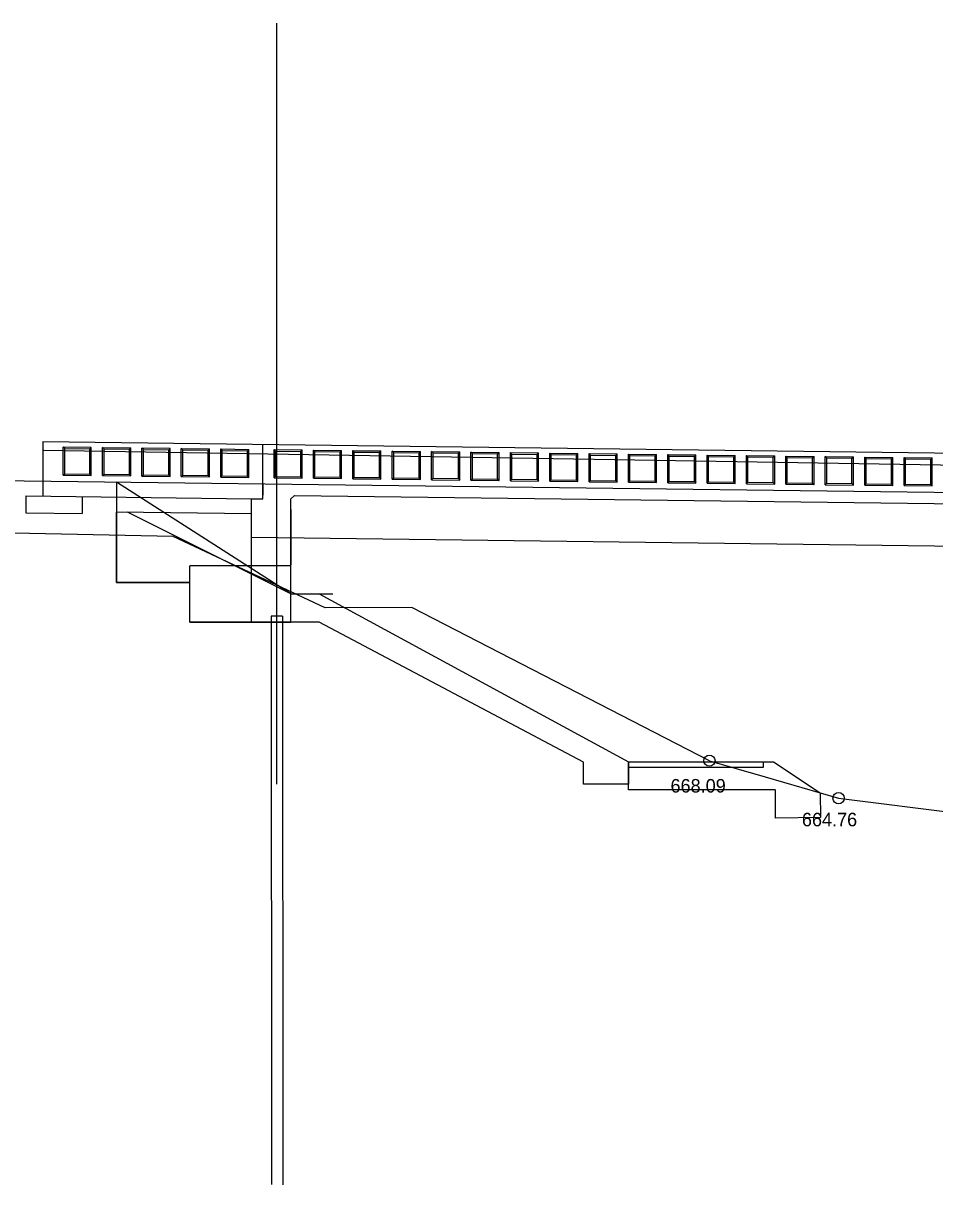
# Model space of a CAD drawing. Extents: x -845213 to 595816, y -257022 to 229056.
# Drawn here: x 595397.5 to 595478.6, y 228657.3 to 228760.5 of the extents above; entities that cross this region are included whole.
import ezdxf

# ---------------------------------------------------------------- set-up
doc = ezdxf.new("R2010")
doc.units = 0
for name, color, linetype in [('B_CL', 7, 'Continuous'), ('B_CONC', 7, 'Continuous'), ('B_CONC_HIDDEN', 7, 'Continuous'), ('B_CONST', 7, 'Continuous'), ('B_GROUNDLINE', 7, 'Continuous'), ('B_MISC', 7, 'Continuous'), ('B_PATTERN', 7, 'Continuous'), ('B_PILES_HIDDEN', 7, 'Continuous'), ('B_PROP', 7, 'Continuous'), ('B_SCREEN', 7, 'Continuous'), ('E_STRUCT', 7, 'Continuous'), ('P_E_PROF', 7, 'Continuous'), ('P_PROF', 7, 'Continuous')]:
    doc.layers.add(name, color=color, linetype=linetype)

msp = doc.modelspace()

# ---------------------------------------------------------------- linework, layer by layer
at = {"layer": 'B_CL'}
for p, q in [((595420.07, 228692.87), (595420.07, 228760.49)), ((595420.07, 228707.28), (595420.07, 228715.45))]:
    msp.add_line(p, q, dxfattribs=at)
at = {"layer": 'B_CONC'}
for p, q in [((595399.25, 228723.31), (595719.75, 228719.29)), ((595399.25, 228723.31), (595399.25, 228719.81)), ((595418.82, 228719.56), (595418.82, 228723.06)), ((595405.82, 228719.72), (595405.82, 228710.78)), ((595421.32, 228718.23), (595421.62, 228718.53)), ((595421.62, 228718.53), (595696.95, 228715.07)), ((595421.32, 228707.28), (595421.32, 228718.23)), ((595417.81, 228714.82), (595700.75, 228711.28)), ((595412.32, 228707.28), (595412.32, 228712.28)), ((595417.82, 228712.28), (595412.32, 228712.28)), ((595405.82, 228710.78), (595412.32, 228710.78))]:
    msp.add_line(p, q, dxfattribs=at)
at = {"layer": 'B_CONC_HIDDEN'}
for p, q in [((595418.82, 228719.56), (595418.82, 228718.56)), ((595417.82, 228718.24), (595418.82, 228718.23)), ((595417.82, 228707.32), (595417.82, 228718.24))]:
    msp.add_line(p, q, dxfattribs=at)
at = {"layer": 'B_CONST'}
for p in [(595421.32, 228717.28), (595421.32, 228707.37)]:
    msp.add_line(p, (595421.32, 228712.37), dxfattribs=at)
at = {"layer": 'B_GROUNDLINE'}
msp.add_lwpolyline([(595421.32, 228709.78), (595405.82, 228719.72)], dxfattribs=at)
at = {"layer": 'B_MISC'}
for p, q in [((595417.82, 228716.88), (595405.82, 228717.05)), ((595405.82, 228710.78), (595405.82, 228717.05)), ((595421.32, 228709.78), (595406.8, 228717.04)), ((595417.82, 228707.28), (595417.82, 228716.88)), ((595421.32, 228712.28), (595412.32, 228712.28)), ((595412.32, 228707.28), (595412.32, 228712.28)), ((595421.32, 228707.28), (595421.32, 228712.28)), ((595412.32, 228710.78), (595405.82, 228710.78)), ((595421.32, 228707.28), (595421.32, 228709.88)), ((595421.32, 228709.78), (595425.04, 228709.78)), ((595421.32, 228707.28), (595412.32, 228707.28))]:
    msp.add_line(p, q, dxfattribs=at)
for centre in [(595458.52, 228694.96), (595470, 228691.63)]:
    msp.add_circle(centre, 0.5, dxfattribs=at)
at = {"layer": 'B_PATTERN'}
for points in [[(595421.32, 228707.28), (595421.32, 228709.78), (595423.82, 228709.78), (595451.32, 228694.87), (595451.32, 228692.87), (595447.32, 228692.87), (595447.32, 228694.83), (595423.82, 228707.28)], [(595451.32, 228692.37), (595451.32, 228694.87), (595464.22, 228694.87), (595468.36, 228692.09), (595468.39, 228689.91), (595464.39, 228689.84), (595464.39, 228692.34), (595464.36, 228692.37)]]:
    msp.add_lwpolyline(points, close=True, dxfattribs=at)
at = {"layer": 'B_PILES_HIDDEN'}
for p, q in [((595420.57, 228707.79), (595419.57, 228707.81)), ((595419.57, 228707.81), (595419.59, 228657.3)), ((595420.57, 228707.79), (595420.59, 228657.28))]:
    msp.add_line(p, q, dxfattribs=at)
at = {"layer": 'B_PROP'}
for p, q in [((595451.32, 228694.87), (595463.32, 228694.87)), ((595451.32, 228694.37), (595451.32, 228694.87)), ((595463.32, 228694.37), (595463.32, 228694.87)), ((595451.32, 228694.37), (595463.32, 228694.37))]:
    msp.add_line(p, q, dxfattribs=at)
at = {"layer": 'B_SCREEN'}
for p, q in [((595403.57, 228722.8), (595401.07, 228722.83)), ((595401.07, 228720.33), (595401.07, 228722.83)), ((595401.2, 228722.7), (595401.07, 228722.83)), ((595401.2, 228722.7), (595403.45, 228722.68)), ((595401.2, 228720.45), (595401.2, 228722.7)), ((595403.45, 228722.68), (595403.57, 228722.8)), ((595403.45, 228720.43), (595403.45, 228722.68)), ((595403.57, 228720.3), (595403.57, 228722.8)), ((595404.57, 228720.29), (595404.57, 228722.79)), ((595404.57, 228722.79), (595407.07, 228722.76)), ((595404.7, 228722.66), (595404.57, 228722.79)), ((595404.7, 228722.66), (595406.95, 228722.63)), ((595404.7, 228720.41), (595404.7, 228722.66)), ((595406.95, 228722.63), (595407.07, 228722.76)), ((595406.95, 228720.38), (595406.95, 228722.63)), ((595407.07, 228720.26), (595407.07, 228722.76)), ((595410.57, 228722.71), (595408.07, 228722.74)), ((595408.07, 228720.24), (595408.07, 228722.74)), ((595408.2, 228722.62), (595408.07, 228722.74)), ((595408.2, 228722.62), (595410.45, 228722.59)), ((595408.2, 228720.37), (595408.2, 228722.62)), ((595410.45, 228722.59), (595410.57, 228722.71)), ((595410.45, 228720.34), (595410.45, 228722.59)), ((595410.57, 228720.21), (595410.57, 228722.71)), ((595411.57, 228720.2), (595411.57, 228722.7)), ((595411.57, 228722.7), (595414.07, 228722.67)), ((595411.7, 228722.57), (595411.57, 228722.7)), ((595411.7, 228722.57), (595413.95, 228722.54)), ((595411.7, 228720.32), (595411.7, 228722.57)), ((595413.95, 228722.54), (595414.07, 228722.67)), ((595413.95, 228720.29), (595413.95, 228722.54)), ((595414.07, 228720.17), (595414.07, 228722.67)), ((595415.07, 228720.16), (595415.07, 228722.66)), ((595415.07, 228722.66), (595417.57, 228722.62)), ((595415.2, 228722.53), (595415.07, 228722.66)), ((595415.2, 228722.53), (595417.45, 228722.5)), ((595415.2, 228720.28), (595415.2, 228722.53)), ((595417.45, 228722.5), (595417.57, 228722.62)), ((595417.57, 228720.12), (595417.57, 228722.62)), ((595419.82, 228720.1), (595419.82, 228722.6)), ((595419.82, 228722.6), (595422.32, 228722.57)), ((595419.95, 228722.47), (595419.82, 228722.6)), ((595422.2, 228722.44), (595422.32, 228722.57)), ((595422.32, 228720.07), (595422.32, 228722.57)), ((595423.32, 228720.05), (595423.32, 228722.55)), ((595423.32, 228722.55), (595425.82, 228722.52)), ((595423.45, 228722.43), (595423.32, 228722.55)), ((595425.7, 228722.4), (595425.82, 228722.52)), ((595425.82, 228720.02), (595425.82, 228722.52)), ((595426.82, 228720.01), (595426.82, 228722.51)), ((595426.82, 228722.51), (595429.32, 228722.48)), ((595426.95, 228722.38), (595426.82, 228722.51)), ((595417.45, 228720.25), (595417.45, 228722.5)), ((595419.95, 228722.47), (595422.2, 228722.44)), ((595419.95, 228720.22), (595419.95, 228722.47)), ((595422.2, 228720.19), (595422.2, 228722.44)), ((595423.45, 228722.43), (595425.7, 228722.4)), ((595423.45, 228720.18), (595423.45, 228722.43)), ((595425.7, 228720.15), (595425.7, 228722.4)), ((595426.95, 228722.38), (595429.2, 228722.36)), ((595426.95, 228720.13), (595426.95, 228722.38)), ((595429.2, 228722.36), (595429.32, 228722.48)), ((595429.2, 228720.11), (595429.2, 228722.36)), ((595429.32, 228719.98), (595429.32, 228722.48)), ((595430.32, 228719.97), (595430.32, 228722.47)), ((595430.32, 228722.47), (595432.82, 228722.44)), ((595430.45, 228722.34), (595430.32, 228722.47)), ((595430.45, 228722.34), (595432.7, 228722.31)), ((595430.45, 228720.09), (595430.45, 228722.34)), ((595432.7, 228722.31), (595432.82, 228722.44)), ((595432.7, 228720.06), (595432.7, 228722.31)), ((595432.82, 228719.94), (595432.82, 228722.44)), ((595433.82, 228719.92), (595433.82, 228722.42)), ((595433.82, 228722.42), (595436.32, 228722.39)), ((595433.95, 228722.3), (595433.82, 228722.42)), ((595433.95, 228722.3), (595436.2, 228722.27)), ((595433.95, 228720.05), (595433.95, 228722.3)), ((595436.2, 228722.27), (595436.32, 228722.39)), ((595436.2, 228720.02), (595436.2, 228722.27)), ((595436.32, 228719.89), (595436.32, 228722.39)), ((595437.32, 228719.88), (595437.32, 228722.38)), ((595437.32, 228722.38), (595439.82, 228722.35)), ((595437.45, 228722.25), (595437.32, 228722.38)), ((595437.45, 228722.25), (595439.69, 228722.22)), ((595437.45, 228720), (595437.45, 228722.25)), ((595439.69, 228722.22), (595439.82, 228722.35)), ((595439.69, 228719.97), (595439.69, 228722.22)), ((595439.82, 228719.85), (595439.82, 228722.35)), ((595440.82, 228719.84), (595440.82, 228722.34)), ((595440.82, 228722.34), (595443.32, 228722.3)), ((595440.94, 228722.21), (595440.82, 228722.34)), ((595440.94, 228722.21), (595443.19, 228722.18)), ((595440.94, 228719.96), (595440.94, 228722.21)), ((595443.19, 228722.18), (595443.32, 228722.3)), ((595443.19, 228719.93), (595443.19, 228722.18)), ((595443.32, 228719.8), (595443.32, 228722.3)), ((595444.32, 228719.79), (595444.32, 228722.29)), ((595444.32, 228722.29), (595446.82, 228722.26)), ((595444.44, 228722.16), (595444.32, 228722.29)), ((595444.44, 228722.16), (595446.69, 228722.14)), ((595444.44, 228719.92), (595444.44, 228722.16)), ((595446.69, 228722.14), (595446.82, 228722.26)), ((595446.69, 228719.89), (595446.69, 228722.14)), ((595446.82, 228719.76), (595446.82, 228722.26)), ((595447.82, 228722.25), (595450.32, 228722.22)), ((595447.82, 228719.75), (595447.82, 228722.25)), ((595447.94, 228722.12), (595447.82, 228722.25)), ((595447.94, 228722.12), (595450.19, 228722.09)), ((595447.94, 228719.87), (595447.94, 228722.12)), ((595450.19, 228722.09), (595450.32, 228722.22)), ((595450.19, 228719.84), (595450.19, 228722.09)), ((595450.32, 228719.72), (595450.32, 228722.22)), ((595451.32, 228719.7), (595451.32, 228722.2)), ((595451.32, 228722.2), (595453.82, 228722.17)), ((595451.44, 228722.08), (595451.32, 228722.2)), ((595451.44, 228722.08), (595453.69, 228722.05)), ((595451.44, 228719.83), (595451.44, 228722.08)), ((595453.69, 228722.05), (595453.82, 228722.17)), ((595453.69, 228719.8), (595453.69, 228722.05)), ((595453.82, 228719.67), (595453.82, 228722.17)), ((595454.82, 228719.66), (595454.82, 228722.16)), ((595454.82, 228722.16), (595457.32, 228722.13)), ((595454.94, 228722.03), (595454.82, 228722.16)), ((595454.94, 228722.03), (595457.19, 228722.01)), ((595454.94, 228719.78), (595454.94, 228722.03)), ((595457.19, 228722.01), (595457.32, 228722.13)), ((595457.19, 228719.76), (595457.19, 228722.01)), ((595457.32, 228719.63), (595457.32, 228722.13)), ((595458.32, 228719.62), (595458.32, 228722.12)), ((595458.32, 228722.12), (595460.82, 228722.08)), ((595458.44, 228721.99), (595458.32, 228722.12)), ((595458.44, 228721.99), (595460.69, 228721.96)), ((595458.44, 228719.74), (595458.44, 228721.99)), ((595460.69, 228721.96), (595460.82, 228722.08)), ((595460.69, 228719.71), (595460.69, 228721.96)), ((595460.82, 228719.58), (595460.82, 228722.08)), ((595461.82, 228719.57), (595461.82, 228722.07)), ((595461.82, 228722.07), (595464.32, 228722.04)), ((595461.94, 228721.95), (595461.82, 228722.07)), ((595461.94, 228721.95), (595464.19, 228721.92)), ((595461.94, 228719.7), (595461.94, 228721.95)), ((595464.19, 228721.92), (595464.32, 228722.04)), ((595464.19, 228719.67), (595464.19, 228721.92)), ((595464.32, 228719.54), (595464.32, 228722.04)), ((595465.32, 228719.53), (595465.32, 228722.03)), ((595465.32, 228722.03), (595467.82, 228722)), ((595465.44, 228721.9), (595465.32, 228722.03)), ((595465.44, 228721.9), (595467.69, 228721.87)), ((595465.44, 228719.65), (595465.44, 228721.9)), ((595467.69, 228721.87), (595467.82, 228722)), ((595467.69, 228719.62), (595467.69, 228721.87)), ((595467.82, 228719.5), (595467.82, 228722)), ((595468.82, 228719.48), (595468.82, 228721.98)), ((595468.82, 228721.98), (595471.32, 228721.95)), ((595468.94, 228721.86), (595468.82, 228721.98)), ((595468.94, 228721.86), (595471.19, 228721.83)), ((595468.94, 228719.61), (595468.94, 228721.86)), ((595471.19, 228721.83), (595471.32, 228721.95)), ((595471.19, 228719.58), (595471.19, 228721.83)), ((595471.32, 228719.45), (595471.32, 228721.95)), ((595472.32, 228719.44), (595472.32, 228721.94)), ((595472.32, 228721.94), (595474.82, 228721.91)), ((595472.44, 228721.81), (595472.32, 228721.94)), ((595472.44, 228721.81), (595474.69, 228721.79)), ((595472.44, 228719.56), (595472.44, 228721.81)), ((595474.69, 228721.79), (595474.82, 228721.91)), ((595474.69, 228719.54), (595474.69, 228721.79)), ((595474.82, 228719.41), (595474.82, 228721.91)), ((595475.82, 228719.4), (595475.82, 228721.9)), ((595475.82, 228721.9), (595478.32, 228721.87)), ((595475.94, 228721.77), (595475.82, 228721.9)), ((595475.94, 228721.77), (595478.19, 228721.74)), ((595475.94, 228719.52), (595475.94, 228721.77)), ((595478.19, 228721.74), (595478.32, 228721.87)), ((595478.19, 228719.49), (595478.19, 228721.74)), ((595478.32, 228719.37), (595478.32, 228721.87)), ((595401.07, 228720.33), (595401.2, 228720.45)), ((595401.2, 228720.45), (595403.45, 228720.43)), ((595401.07, 228720.33), (595403.57, 228720.3)), ((595403.45, 228720.43), (595403.57, 228720.3)), ((595404.57, 228720.29), (595404.7, 228720.41)), ((595404.57, 228720.29), (595407.07, 228720.26)), ((595404.7, 228720.41), (595406.95, 228720.38)), ((595406.95, 228720.38), (595407.07, 228720.26)), ((595408.07, 228720.24), (595408.2, 228720.37)), ((595408.07, 228720.24), (595410.57, 228720.21)), ((595408.2, 228720.37), (595410.45, 228720.34)), ((595410.45, 228720.34), (595410.57, 228720.21)), ((595411.57, 228720.2), (595411.7, 228720.32)), ((595411.57, 228720.2), (595414.07, 228720.17)), ((595411.7, 228720.32), (595413.95, 228720.29)), ((595413.95, 228720.29), (595414.07, 228720.17)), ((595415.07, 228720.16), (595415.2, 228720.28)), ((595415.07, 228720.16), (595417.57, 228720.12)), ((595415.2, 228720.28), (595417.45, 228720.25)), ((595417.45, 228720.25), (595417.57, 228720.12)), ((595419.82, 228720.1), (595419.95, 228720.22)), ((595419.82, 228720.1), (595422.32, 228720.07)), ((595419.95, 228720.22), (595422.2, 228720.19)), ((595422.2, 228720.19), (595422.32, 228720.07)), ((595423.32, 228720.05), (595423.45, 228720.18)), ((595423.32, 228720.05), (595425.82, 228720.02)), ((595423.45, 228720.18), (595425.7, 228720.15)), ((595425.7, 228720.15), (595425.82, 228720.02)), ((595426.82, 228720.01), (595426.95, 228720.13)), ((595426.82, 228720.01), (595429.32, 228719.98)), ((595426.95, 228720.13), (595429.2, 228720.11)), ((595429.2, 228720.11), (595429.32, 228719.98)), ((595430.32, 228719.97), (595430.45, 228720.09)), ((595430.32, 228719.97), (595432.82, 228719.94)), ((595430.45, 228720.09), (595432.7, 228720.06)), ((595432.7, 228720.06), (595432.82, 228719.94)), ((595433.82, 228719.92), (595433.95, 228720.05)), ((595433.82, 228719.92), (595436.32, 228719.89)), ((595433.95, 228720.05), (595436.2, 228720.02)), ((595436.2, 228720.02), (595436.32, 228719.89)), ((595437.32, 228719.88), (595437.45, 228720)), ((595437.32, 228719.88), (595439.82, 228719.85)), ((595437.45, 228720), (595439.69, 228719.97)), ((595439.69, 228719.97), (595439.82, 228719.85)), ((595440.82, 228719.84), (595440.94, 228719.96)), ((595440.82, 228719.84), (595443.32, 228719.8)), ((595440.94, 228719.96), (595443.19, 228719.93)), ((595443.19, 228719.93), (595443.32, 228719.8)), ((595444.32, 228719.79), (595444.44, 228719.92)), ((595444.32, 228719.79), (595446.82, 228719.76)), ((595444.44, 228719.92), (595446.69, 228719.89)), ((595446.69, 228719.89), (595446.82, 228719.76)), ((595447.82, 228719.75), (595447.94, 228719.87)), ((595447.82, 228719.75), (595450.32, 228719.72)), ((595447.94, 228719.87), (595450.19, 228719.84)), ((595450.19, 228719.84), (595450.32, 228719.72)), ((595451.32, 228719.7), (595451.44, 228719.83)), ((595451.32, 228719.7), (595453.82, 228719.67)), ((595451.44, 228719.83), (595453.69, 228719.8)), ((595453.69, 228719.8), (595453.82, 228719.67)), ((595454.82, 228719.66), (595454.94, 228719.78)), ((595454.82, 228719.66), (595457.32, 228719.63)), ((595454.94, 228719.78), (595457.19, 228719.76)), ((595457.19, 228719.76), (595457.32, 228719.63)), ((595458.32, 228719.62), (595458.44, 228719.74)), ((595458.32, 228719.62), (595460.82, 228719.58)), ((595458.44, 228719.74), (595460.69, 228719.71)), ((595460.69, 228719.71), (595460.82, 228719.58)), ((595461.82, 228719.57), (595461.94, 228719.7)), ((595461.82, 228719.57), (595464.32, 228719.54)), ((595461.94, 228719.7), (595464.19, 228719.67)), ((595464.19, 228719.67), (595464.32, 228719.54)), ((595465.32, 228719.53), (595465.44, 228719.65)), ((595465.32, 228719.53), (595467.82, 228719.5)), ((595465.44, 228719.65), (595467.69, 228719.62)), ((595467.69, 228719.62), (595467.82, 228719.5)), ((595468.82, 228719.48), (595468.94, 228719.61)), ((595468.82, 228719.48), (595471.32, 228719.45)), ((595468.94, 228719.61), (595471.19, 228719.58)), ((595471.19, 228719.58), (595471.32, 228719.45)), ((595472.32, 228719.44), (595472.44, 228719.56)), ((595472.32, 228719.44), (595474.82, 228719.41)), ((595472.44, 228719.56), (595474.69, 228719.54)), ((595474.69, 228719.54), (595474.82, 228719.41)), ((595475.82, 228719.4), (595475.94, 228719.52)), ((595475.94, 228719.52), (595478.19, 228719.49)), ((595478.19, 228719.49), (595478.32, 228719.37)), ((595475.82, 228719.4), (595478.32, 228719.37))]:
    msp.add_line(p, q, dxfattribs=at)
at = {"layer": 'E_STRUCT'}
msp.add_line((595399.35, 228722.55), (595731.51, 228717.17), dxfattribs=at)
at = {"layer": 'P_E_PROF'}
for p, q in [((595410.85, 228714.88), (595356.93, 228715.96)), ((595424.36, 228708.54), (595410.85, 228714.88)), ((595432.05, 228708.58), (595424.36, 228708.54)), ((595458.52, 228694.96), (595432.05, 228708.58)), ((595458.52, 228694.96), (595463.48, 228693.52)), ((595463.48, 228693.52), (595470, 228691.63)), ((595470, 228691.63), (595481.13, 228690.24))]:
    msp.add_line(p, q, dxfattribs=at)
at = {"layer": 'P_PROF'}
for p, q in [((595315.56, 228720.86), (595815.56, 228714.59)), ((595399.25, 228719.81), (595399.25, 228718.47)), ((595418.82, 228718.23), (595418.82, 228719.56)), ((595397.75, 228718.49), (595397.75, 228716.99)), ((595397.75, 228718.49), (595417.82, 228718.24)), ((595402.75, 228718.43), (595402.75, 228716.93)), ((595397.75, 228716.99), (595402.75, 228716.93)), ((595412.32, 228707.28), (595421.32, 228707.28))]:
    msp.add_line(p, q, dxfattribs=at)

# ---------------------------------------------------------------- texts
at = {"layer": 'B_MISC'}
for s, p in [('668.09', (595455.06, 228692.13)), ('664.76', (595466.74, 228689.13))]:
    msp.add_text(s, height=1.2, dxfattribs=at).set_placement(p)

doc.saveas('drawing.dxf')
